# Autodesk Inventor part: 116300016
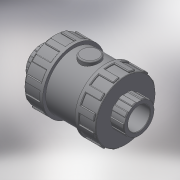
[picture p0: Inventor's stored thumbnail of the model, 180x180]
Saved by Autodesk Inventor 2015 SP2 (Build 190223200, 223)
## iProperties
Created: 2017-11
Part Number: 116300016
Material: Generic
Description: PLASSON AIR RELEASE VALVE CEM PVC 16
Document SubType Name: Modeling
Designer: KIM
Density: 1 g/cm^3
Appearance: Default
Author: KIM
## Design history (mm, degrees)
derived "116300 - 116900.ipt"
feature "Solid1::116300 - 116900.ipt"
tag "TaggingFeature1"
body "Solid1"
other parameters: "d0" = 71, "d1" = 16, "d2" = 45, "d3" = 14, "d4" = 12.8, "d5" = 9.8, "d7" = 22.4, "d8" = 40.5, "d13" = 0.48, "d23" = 14, "d24" = 43.2, "d25" = 0.32, "d26" = 0.48, "d27" = 6.75, "d28" = 3.375, "d29" = 10.5, "d30" = 0, "d35" = 0.48, "d39" = 22.5, "d45" = 360 deg, "d47" = 0.32, "d50" = 22.5, "d51" = 13.5, "d53" = 0, "d54" = 0.9, "d55" = 3.2, "d56" = 1.6, "d58" = 0, "d59" = 0.48, "d61" = 360 deg, "d_" = 16, "l_" = 14, "H_" = 71, "K_" = 45
